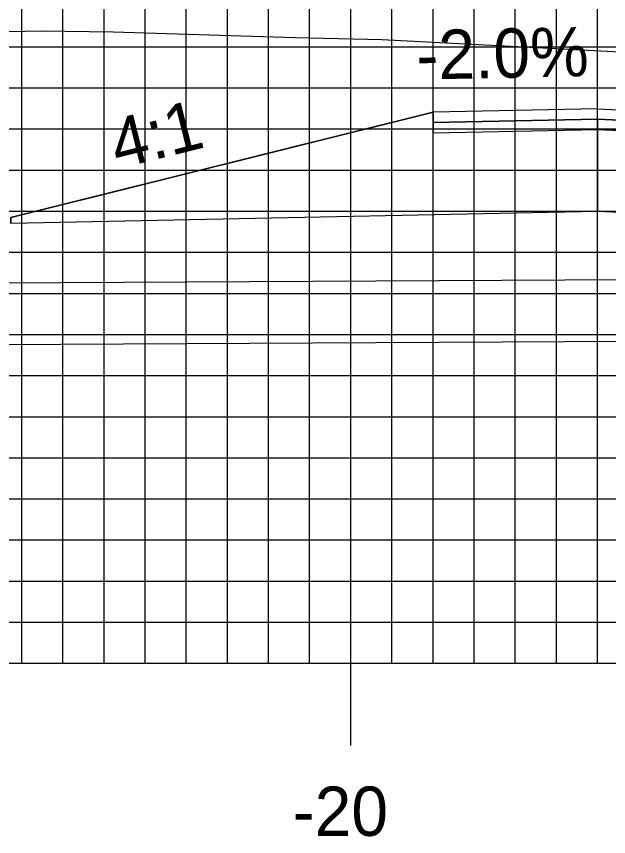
# Model space of a CAD drawing. Extents: x 1685192 to 1685536, y 461260 to 461480.
# Drawn here: x 1685330.1 to 1685344.5, y 461420.99 to 461440.95 of the extents above; entities that cross this region are included whole.
import ezdxf

# ---------------------------------------------------------------- set-up
doc = ezdxf.new("R2010")
doc.units = 0
for name, color, linetype in [('ANNOTATION', 7, 'Continuous'), ('D_Drainage_Culvert', 7, 'Continuous'), ('D_Roadway_Edge_Shoulder', 7, 'Continuous'), ('D_Roadway_Edge_TW', 7, 'Continuous'), ('D_Roadway_FinishedGrade', 7, 'Continuous'), ('D_Roadway_Pavement', 7, 'Continuous'), ('D_Roadway_SlopeLines', 7, 'Continuous'), ('D_Roadway_SubGrade', 7, 'Continuous'), ('H_V ANNOTATION', 7, 'Continuous'), ('M_Roadway_Centerline', 7, 'Continuous'), ('MAJOR', 7, 'Continuous'), ('MINOR', 7, 'Continuous'), ('S_Roadway_Centerline', 7, 'Continuous')]:
    doc.layers.add(name, color=color, linetype=linetype)

msp = doc.modelspace()

# ---------------------------------------------------------------- linework, layer by layer
at = {"layer": 'D_Drainage_Culvert'}
for p, q in [((1685323.713, 461434.435), (1685379.832, 461434.716)), ((1685323.713, 461432.935), (1685379.839, 461433.216))]:
    msp.add_line(p, q, dxfattribs=at)
at = {"layer": 'D_Roadway_Edge_Shoulder'}
for points in [[(1685344.229, 461438.695), (1685340.229, 461438.615), (1685340.229, 461438.365), (1685344.229, 461438.445)], [(1685344.229, 461438.445), (1685340.229, 461438.365), (1685340.229, 461438.115), (1685344.229, 461438.195)]]:
    msp.add_lwpolyline(points, close=True, dxfattribs=at)
at = {"layer": 'D_Roadway_Edge_TW'}
msp.add_lwpolyline([(1685344.229, 461438.695), (1685358.229, 461438.051), (1685358.229, 461437.801), (1685344.229, 461438.445)], close=True, dxfattribs=at)
at = {"layer": 'D_Roadway_FinishedGrade'}
msp.add_lwpolyline([(1685340.229, 461438.615), (1685336.229, 461437.615), (1685329.965, 461436.049)], dxfattribs=at)
at = {"layer": 'D_Roadway_Pavement'}
msp.add_lwpolyline([(1685344.229, 461438.445), (1685358.229, 461437.801), (1685358.229, 461437.551), (1685344.229, 461438.195)], close=True, dxfattribs=at)
msp.add_lwpolyline([(1685344.229, 461438.445), (1685344.229, 461438.195)], dxfattribs=at)
msp.add_lwpolyline([(1685344.229, 461438.445), (1685344.229, 461438.195)], dxfattribs=at)
at = {"layer": 'D_Roadway_SlopeLines'}
msp.add_lwpolyline([(1685340.229, 461438.615), (1685329.965, 461436.049), (1685329.965, 461435.91)], dxfattribs=at)
at = {"layer": 'D_Roadway_SubGrade'}
for points in [[(1685344.229, 461436.195), (1685329.965, 461435.91), (1685329.965, 461436.049), (1685340.229, 461438.615), (1685340.229, 461438.365), (1685344.229, 461438.445), (1685344.229, 461438.195)], [(1685344.229, 461438.195), (1685358.229, 461437.551), (1685358.229, 461435.551), (1685344.229, 461436.195)]]:
    msp.add_lwpolyline(points, close=True, dxfattribs=at)
at = {"layer": 'MAJOR'}
for p, q in [((1685338.229, 461425.206), (1685338.229, 461450.206)), ((1685218.229, 461440.206), (1685498.229, 461440.206)), ((1685218.229, 461435.206), (1685498.229, 461435.206)), ((1685218.229, 461430.206), (1685498.229, 461430.206)), ((1685218.229, 461425.206), (1685498.229, 461425.206)), ((1685218.229, 461425.206), (1685498.229, 461425.206)), ((1685338.229, 461423.202), (1685338.229, 461425.206))]:
    msp.add_line(p, q, dxfattribs=at)
at = {"layer": 'MINOR'}
for p, q in [((1685330.229, 461425.206), (1685330.229, 461450.206)), ((1685331.229, 461425.206), (1685331.229, 461450.206)), ((1685332.229, 461425.206), (1685332.229, 461450.206)), ((1685333.229, 461425.206), (1685333.229, 461450.206)), ((1685334.229, 461425.206), (1685334.229, 461450.206)), ((1685335.229, 461425.206), (1685335.229, 461450.206)), ((1685336.229, 461425.206), (1685336.229, 461450.206)), ((1685337.229, 461425.206), (1685337.229, 461450.206)), ((1685339.229, 461425.206), (1685339.229, 461450.206)), ((1685340.229, 461425.206), (1685340.229, 461450.206)), ((1685341.229, 461425.206), (1685341.229, 461450.206)), ((1685342.229, 461425.206), (1685342.229, 461450.206)), ((1685343.229, 461425.206), (1685343.229, 461450.206)), ((1685344.229, 461425.206), (1685344.229, 461450.206)), ((1685218.229, 461439.206), (1685498.229, 461439.206)), ((1685218.229, 461438.206), (1685498.229, 461438.206)), ((1685218.229, 461437.206), (1685498.229, 461437.206)), ((1685218.229, 461436.206), (1685498.229, 461436.206)), ((1685218.229, 461434.206), (1685498.229, 461434.206)), ((1685218.229, 461433.206), (1685498.229, 461433.206)), ((1685218.229, 461432.206), (1685498.229, 461432.206)), ((1685218.229, 461431.206), (1685498.229, 461431.206)), ((1685218.229, 461429.206), (1685498.229, 461429.206)), ((1685218.229, 461428.206), (1685498.229, 461428.206)), ((1685218.229, 461427.206), (1685498.229, 461427.206)), ((1685218.229, 461426.206), (1685498.229, 461426.206))]:
    msp.add_line(p, q, dxfattribs=at)
at = {"layer": 'S_Roadway_Centerline'}
msp.add_lwpolyline([(1685286.43, 461435.332), (1685288.431, 461435.437), (1685289.361, 461435.639), (1685289.912, 461435.758), (1685306.542, 461439.532), (1685306.637, 461439.548), (1685308.936, 461439.765), (1685313.647, 461440.214), (1685314.316, 461440.255), (1685330.697, 461440.593), (1685332.454, 461440.571), (1685336.875, 461440.432), (1685338.988, 461440.38), (1685348.379, 461439.9), (1685358.138, 461440.263), (1685360.692, 461440.305), (1685367.617, 461440.119), (1685369.76, 461440.052), (1685370.232, 461439.98), (1685380.088, 461439.409), (1685388.173, 461438.92)], dxfattribs=at)

# ---------------------------------------------------------------- texts
at = {"layer": 'ANNOTATION'}
for s, rotation, p in [('-2.0%', 1.1458, (1685339.836, 461439.407)), ('4:1', 14.0362, (1685332.557, 461437.228))]:
    msp.add_text(s, height=1.2, rotation=rotation, dxfattribs=at).set_placement(p)
at = {"layer": 'H_V ANNOTATION'}
msp.add_text('-20', height=1.2, dxfattribs=at).set_placement((1685336.816, 461421.006))
at = {"layer": 'M_Roadway_Centerline'}
for s, p in [('C', (1685332.448, 461440.571)), ('L', (1685332.454, 461440.563))]:
    msp.add_text(s, height=0.0146, dxfattribs=at).set_placement(p)

doc.saveas('drawing.dxf')
